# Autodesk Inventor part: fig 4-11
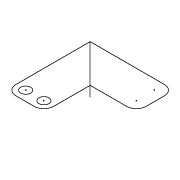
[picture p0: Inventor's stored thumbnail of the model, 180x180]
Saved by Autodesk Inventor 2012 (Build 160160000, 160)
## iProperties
Created: 2005-02
Part Number: fig 4-11
Document SubType Name: Modeling
Designer: CADCIM
Manufacturer: Standard
Standards Organization: Custom
Density: 1 g/cm^3
Material: Default
Author: CADCIM
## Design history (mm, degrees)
sketch "Sketch1"
  geometry: L1 (5.141, 24.979)-(-32.827, 24.979); L2 (-32.827, 24.979)-(-32.827, -12.989); L3 (-27.827, -17.989)-(-18.492, -17.989); L4 (-13.492, -12.989)-(-13.492, 5.644); L5 (-13.492, 5.644)-(5.141, 5.644); L6 (10.141, 10.644)-(10.141, 19.979); L7 (-32.827, 24.979)-(-8.203, 0.354); C1 r 2.58 at (-27.827, -12.989); C2 r 2.58 at (-18.492, -12.989); A1 r 5 centre (-27.827, -12.989) between (-32.827, -12.989) and (-27.827, -17.989); A2 r 5 centre (-18.492, -12.989) between (-18.492, -17.989) and (-13.492, -12.989); A3 r 5 centre (5.141, 10.644) between (5.141, 5.644) and (10.141, 10.644); A4 r 5 centre (5.141, 19.979) between (10.141, 19.979) and (5.141, 24.979)
  constraints: 14 end point, 8 point on circle, 8 tangent, 6 centre point, 4 equal radius, 4 parallel, 3 perpendicular, 2 coincident, 1 horizontal, 1 point on line
